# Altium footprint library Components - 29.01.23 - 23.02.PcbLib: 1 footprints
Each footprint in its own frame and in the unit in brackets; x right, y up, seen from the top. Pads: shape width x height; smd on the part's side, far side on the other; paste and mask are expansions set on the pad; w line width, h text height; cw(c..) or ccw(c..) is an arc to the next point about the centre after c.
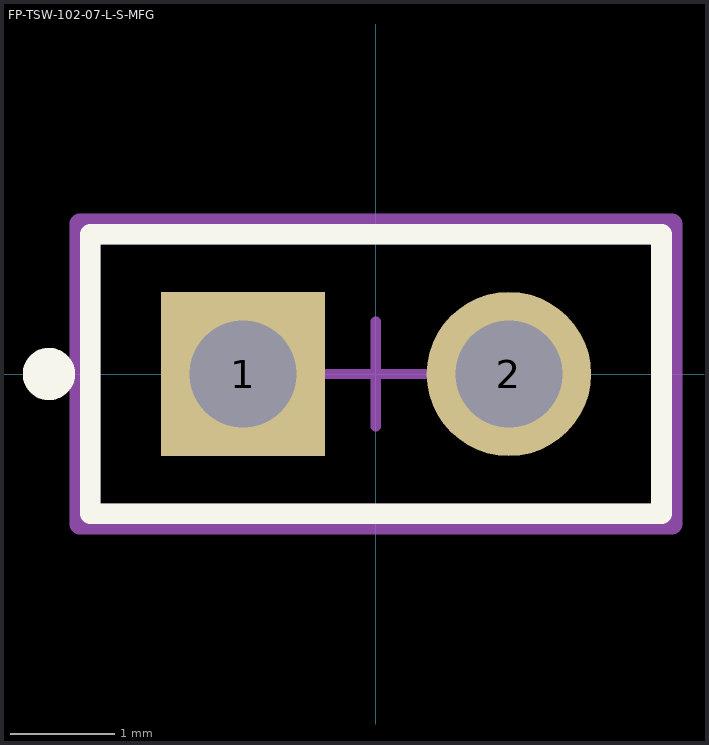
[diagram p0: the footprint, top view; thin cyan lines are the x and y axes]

## FP-TSW-102-07-L-S-MFG [mm]
pads (2):
  rect 1.57x1.57 hole 1.02 paste-1000 mask+0: 1(-1.27,0)
  round 1.57 hole 1.02 paste-1000 mask+0: 2(1.27,0)
Top Overlay:
  circle w0.25: c-3.125,0 r0.125
  lines w0.2: -2.73,-1.335 -2.73,1.335 2.73,1.335 2.73,-1.335 -2.73,-1.335
Top Assembly:
  lines w0.2: -2.83,-1.435 -2.83,1.435 2.83,1.435 2.83,-1.435 -2.83,-1.435
  text ".Designator" at 0,0.188 h1
Top 3D Body:
  lines w0.2: -2.73,-1.335 -2.73,1.335 2.73,1.335 2.73,-1.335 -2.73,-1.335
Top Courtyard:
  lines w0.2: -2.83,-1.435 -2.83,1.435 2.83,1.435 2.83,-1.435 -2.83,-1.435
Top Component Center:
  lines w0.1: -0.5,0 0.5,0 ; 0,-0.5 0,0.5
3D body "Conn_SAMTEC_TSW-102-07-L-S_eec.STEP": height 0.25, standoff 0, extent -2.83,-1.435 2.83,1.435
